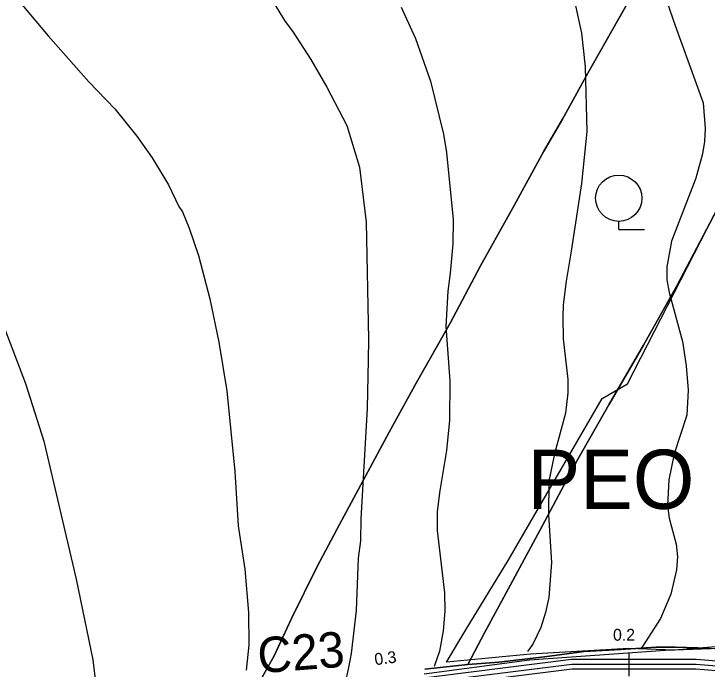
# Model space of a CAD drawing. Extents: x -662620 to -656370, y -1067090 to -1062990.
# Drawn here: x -658981.3 to -658688.1, y -1066386.4 to -1066109.2 of the extents above; entities that cross this region are included whole.
import ezdxf

# ---------------------------------------------------------------- set-up
doc = ezdxf.new("R2010")
doc.units = 0
for name, color, linetype in [('Default', 7, 'Continuous'), ('HRANICE_KATASTRÁLNÍHO_ÚZEMÍ', 7, 'Continuous'), ('Organizacni_opatreni_ochranne_zatravnení__protierozni_rozmistovani_plodin__osevni_postup__stridani_plodin', 7, 'Continuous'), ('ORNÁ_PŮDA_-_STÁVAJÍCÍ', 7, 'Continuous'), ('OSTATNÍ_PLOCHA_-_STÁVAJÍCÍ', 7, 'Continuous'), ('OVOCNÝ_SAD_-_STÁVAJÍCÍ', 7, 'Continuous'), ('OVOCNÝ_SAD_-_ZNAČKA', 7, 'Continuous'), ('POLNÍ_CESTA_STÁVAJÍCÍ_-_KRAJ', 7, 'Continuous'), ('POLNÍ_CESTA_STÁVAJÍCÍ_-_OSA', 7, 'Continuous'), ('Popis_objektú_polních_cest_stávajících', 7, 'Continuous'), ('VRSTEVNICE_ZDŮRAZNĚNÁ', 7, 'Continuous'), ('VRSTEVNICE_ZÁKLADNÍ', 7, 'Continuous')]:
    doc.layers.add(name, color=color, linetype=linetype)

msp = doc.modelspace()

# ---------------------------------------------------------------- linework, layer by layer
at = {"layer": 'HRANICE_KATASTRÁLNÍHO_ÚZEMÍ'}
msp.add_lwpolyline([(-658807.8, -1066388.34), (-658763.27, -1066382.42), (-658705.81, -1066378.41), (-658644.15, -1066376.09), (-658640.46, -1066376.58), (-658612.67, -1066385.38), (-658599.32, -1066389.61)], dxfattribs=at)
at = {"layer": 'Organizacni_opatreni_ochranne_zatravnení__protierozni_rozmistovani_plodin__osevni_postup__stridani_plodin'}
msp.add_lwpolyline([(-658515.32, -1066087.97), (-658611.96, -1066385.11), (-658646.2, -1066373.85), (-658701.92, -1066378.35), (-658721.2, -1066377.7), (-658762.8, -1066380.1), (-658798.28, -1066383.49), (-658790.2, -1066369.8), (-658772.2, -1066340.5), (-658732.5, -1066271.9), (-658721.7, -1066265.7), (-658679.4, -1066183.2), (-658621.96, -1066065.74), (-658571.37, -1066075.89), (-658543.99, -1066081.97)], close=True, dxfattribs=at)
at = {"layer": 'ORNÁ_PŮDA_-_STÁVAJÍCÍ'}
for p, q in [((-658713.12, -1066089.31), (-658725.43, -1066111.17)), ((-658725.43, -1066111.17), (-658738.48, -1066134.29)), ((-658738.48, -1066134.29), (-658749.28, -1066153.83)), ((-658749.28, -1066153.83), (-658757.17, -1066167.26)), ((-658757.17, -1066167.26), (-658769.64, -1066190.35)), ((-658769.64, -1066190.35), (-658783.88, -1066215.86)), ((-658700.9, -1066224.3), (-658683.93, -1066192.16)), ((-658783.88, -1066215.86), (-658796.78, -1066240.04)), ((-658714.94, -1066249.3), (-658700.9, -1066224.3)), ((-658796.78, -1066240.04), (-658810.97, -1066265.15)), ((-658729.63, -1066274.64), (-658714.94, -1066249.3)), ((-658810.97, -1066265.15), (-658822.53, -1066286.09)), ((-658742.91, -1066297.84), (-658729.63, -1066274.64)), ((-658822.53, -1066286.09), (-658832.6, -1066304.76)), ((-658758.91, -1066327.69), (-658742.91, -1066297.84)), ((-658832.6, -1066304.76), (-658843.53, -1066325.14)), ((-658843.53, -1066325.14), (-658853.1, -1066342.96)), ((-658773.05, -1066354.13), (-658758.91, -1066327.69)), ((-658853.1, -1066342.96), (-658863.83, -1066364.98)), ((-658782.28, -1066371.01), (-658773.05, -1066354.13)), ((-658863.83, -1066364.98), (-658871.22, -1066380.79)), ((-658789.25, -1066384.41), (-658782.28, -1066371.01)), ((-658709.66, -1066377.1), (-658724.68, -1066378.11)), ((-658701.54, -1066377.15), (-658709.66, -1066377.1)), ((-658740.07, -1066378.97), (-658756.9, -1066381.11)), ((-658724.68, -1066378.11), (-658740.07, -1066378.97)), ((-658687.26, -1066377.58), (-658701.54, -1066377.15)), ((-658871.22, -1066380.79), (-658877.55, -1066391.99)), ((-658756.9, -1066381.11), (-658776.23, -1066383.42)), ((-658776.23, -1066383.42), (-658789.25, -1066384.41))]:
    msp.add_line(p, q, dxfattribs=at)
for points in [[(-658713.12, -1066089.31), (-658725.43, -1066111.17), (-658738.48, -1066134.29), (-658749.28, -1066153.83), (-658757.17, -1066167.26), (-658769.64, -1066190.35), (-658783.88, -1066215.86), (-658796.78, -1066240.04), (-658810.97, -1066265.15), (-658822.53, -1066286.09), (-658832.6, -1066304.76), (-658843.53, -1066325.14), (-658853.1, -1066342.96), (-658863.83, -1066364.98), (-658871.22, -1066380.79), (-658877.55, -1066391.99)], [(-658687.26, -1066377.58), (-658701.54, -1066377.15), (-658709.66, -1066377.1), (-658724.68, -1066378.11), (-658740.07, -1066378.97), (-658756.9, -1066381.11), (-658776.23, -1066383.42), (-658789.25, -1066384.41), (-658782.28, -1066371.01), (-658773.05, -1066354.13), (-658758.91, -1066327.69), (-658742.91, -1066297.84), (-658729.63, -1066274.64), (-658714.94, -1066249.3), (-658700.9, -1066224.3), (-658683.93, -1066192.16)]]:
    msp.add_lwpolyline(points, dxfattribs=at)
at = {"layer": 'OSTATNÍ_PLOCHA_-_STÁVAJÍCÍ'}
for p, q in [((-658724.68, -1066378.11), (-658709.66, -1066377.1)), ((-658724.68, -1066378.11), (-658709.66, -1066377.1)), ((-658709.66, -1066377.1), (-658701.54, -1066377.15)), ((-658709.66, -1066377.1), (-658701.54, -1066377.15)), ((-658756.9, -1066381.11), (-658740.07, -1066378.97)), ((-658756.9, -1066381.11), (-658740.07, -1066378.97)), ((-658740.07, -1066378.97), (-658724.68, -1066378.11)), ((-658740.07, -1066378.97), (-658724.68, -1066378.11)), ((-658701.54, -1066377.15), (-658687.26, -1066377.58)), ((-658701.54, -1066377.15), (-658687.26, -1066377.58)), ((-658776.23, -1066383.42), (-658756.9, -1066381.11)), ((-658776.23, -1066383.42), (-658756.9, -1066381.11)), ((-658807.43, -1066386.38), (-658789.25, -1066384.41)), ((-658807.43, -1066386.38), (-658789.25, -1066384.41)), ((-658789.25, -1066384.41), (-658776.23, -1066383.42)), ((-658789.25, -1066384.41), (-658776.23, -1066383.42))]:
    msp.add_line(p, q, dxfattribs=at)
msp.add_lwpolyline([(-658807.43, -1066386.38), (-658789.25, -1066384.41), (-658776.23, -1066383.42), (-658756.9, -1066381.11), (-658740.07, -1066378.97), (-658724.68, -1066378.11), (-658709.66, -1066377.1), (-658701.54, -1066377.15), (-658687.26, -1066377.58), (-658672.12, -1066378.24), (-658659, -1066379.52), (-658644.1, -1066381.07), (-658627.93, -1066382.83), (-658615.46, -1066385), (-658583.4, -1066395.38)], dxfattribs=at)
msp.add_lwpolyline([(-658807.43, -1066386.38), (-658789.25, -1066384.41), (-658776.23, -1066383.42), (-658756.9, -1066381.11), (-658740.07, -1066378.97), (-658724.68, -1066378.11), (-658709.66, -1066377.1), (-658701.54, -1066377.15), (-658687.26, -1066377.58), (-658672.12, -1066378.24), (-658659, -1066379.52), (-658644.1, -1066381.07), (-658627.93, -1066382.83), (-658615.46, -1066385), (-658583.4, -1066395.38)], dxfattribs=at)
at = {"layer": 'OVOCNÝ_SAD_-_STÁVAJÍCÍ'}
for p, q in [((-658725.43, -1066111.17), (-658713.12, -1066089.31)), ((-658738.48, -1066134.29), (-658725.43, -1066111.17)), ((-658749.28, -1066153.83), (-658738.48, -1066134.29)), ((-658757.17, -1066167.26), (-658749.28, -1066153.83)), ((-658769.64, -1066190.35), (-658757.17, -1066167.26)), ((-658783.88, -1066215.86), (-658769.64, -1066190.35)), ((-658683.93, -1066192.16), (-658700.9, -1066224.3)), ((-658796.78, -1066240.04), (-658783.88, -1066215.86)), ((-658700.9, -1066224.3), (-658714.94, -1066249.3)), ((-658810.97, -1066265.15), (-658796.78, -1066240.04)), ((-658714.94, -1066249.3), (-658729.63, -1066274.64)), ((-658822.53, -1066286.09), (-658810.97, -1066265.15)), ((-658729.63, -1066274.64), (-658742.91, -1066297.84)), ((-658832.6, -1066304.76), (-658822.53, -1066286.09)), ((-658742.91, -1066297.84), (-658758.91, -1066327.69)), ((-658843.53, -1066325.14), (-658832.6, -1066304.76)), ((-658853.1, -1066342.96), (-658843.53, -1066325.14)), ((-658758.91, -1066327.69), (-658773.05, -1066354.13)), ((-658863.83, -1066364.98), (-658853.1, -1066342.96)), ((-658773.05, -1066354.13), (-658782.28, -1066371.01)), ((-658871.22, -1066380.79), (-658863.83, -1066364.98)), ((-658782.28, -1066371.01), (-658789.25, -1066384.41)), ((-658877.55, -1066391.99), (-658871.22, -1066380.79)), ((-658789.25, -1066384.41), (-658807.43, -1066386.38))]:
    msp.add_line(p, q, dxfattribs=at)
for points in [[(-658877.55, -1066391.99), (-658871.22, -1066380.79), (-658863.83, -1066364.98), (-658853.1, -1066342.96), (-658843.53, -1066325.14), (-658832.6, -1066304.76), (-658822.53, -1066286.09), (-658810.97, -1066265.15), (-658796.78, -1066240.04), (-658783.88, -1066215.86), (-658769.64, -1066190.35), (-658757.17, -1066167.26), (-658749.28, -1066153.83), (-658738.48, -1066134.29), (-658725.43, -1066111.17), (-658713.12, -1066089.31)], [(-658633.64, -1066100.29), (-658649.35, -1066128.19), (-658665.84, -1066158.69), (-658683.93, -1066192.16), (-658700.9, -1066224.3), (-658714.94, -1066249.3), (-658729.63, -1066274.64), (-658742.91, -1066297.84), (-658758.91, -1066327.69), (-658773.05, -1066354.13), (-658782.28, -1066371.01), (-658789.25, -1066384.41), (-658807.43, -1066386.38)]]:
    msp.add_lwpolyline(points, dxfattribs=at)
at = {"layer": 'OVOCNÝ_SAD_-_ZNAČKA'}
for points in [[(-658725.47, -1066200.47), (-658725.47, -1066197)], [(-658725.47, -1066200.47), (-658714.63, -1066200.47)]]:
    msp.add_lwpolyline(points, dxfattribs=at)
msp.add_circle((-658725.47, -1066187.21), 9.79, dxfattribs=at)
at = {"layer": 'POLNÍ_CESTA_STÁVAJÍCÍ_-_KRAJ'}
for points in [[(-658524.77, -1066416.91), (-658585.14, -1066399.5), (-658627.95, -1066387.63), (-658692.63, -1066382.35), (-658745.41, -1066382.35), (-658844.82, -1066394.86), (-658910.58, -1066405.85), (-659008.67, -1066433.22), (-659055.89, -1066439.26), (-659092.46, -1066437.38), (-659149.26, -1066425.87), (-659161.27, -1066431.66), (-659178.7, -1066451.74), (-659206.01, -1066461.71), (-659282.28, -1066460.95), (-659319.31, -1066453.29)], [(-658525.87, -1066420.75), (-658586.23, -1066403.35), (-658628.66, -1066391.58), (-658692.79, -1066386.35), (-658745.16, -1066386.35), (-658844.24, -1066398.82), (-658909.71, -1066409.76), (-659007.88, -1066437.15), (-659055.74, -1066443.28), (-659092.96, -1066441.36), (-659148.74, -1066430.05), (-659158.79, -1066434.91), (-659176.35, -1066455.14), (-659205.33, -1066465.71), (-659282.71, -1066464.95), (-659320.12, -1066457.21)]]:
    msp.add_lwpolyline(points, dxfattribs=at)
at = {"layer": 'POLNÍ_CESTA_STÁVAJÍCÍ_-_OSA'}
for points in [[(-658721.04, -1066389.35), (-658721.04, -1066379.35)], [(-658525.32, -1066418.83), (-658585.69, -1066401.42), (-658628.3, -1066389.61), (-658692.71, -1066384.35), (-658745.29, -1066384.35), (-658844.53, -1066396.84), (-658910.15, -1066407.8), (-659008.28, -1066435.19), (-659055.82, -1066441.27), (-659092.71, -1066439.37), (-659149, -1066427.96), (-659160.03, -1066433.28), (-659177.52, -1066453.44), (-659205.67, -1066463.71), (-659282.5, -1066462.95), (-659319.71, -1066455.25)]]:
    msp.add_lwpolyline(points, dxfattribs=at)
at = {"layer": 'VRSTEVNICE_ZDŮRAZNĚNÁ'}
for points in [[(-658707.22, -1066097.88), (-658701.63, -1066114.21), (-658689.74, -1066146.89), (-658688.88, -1066157.78), (-658689.16, -1066163.23), (-658690.02, -1066168.39), (-658692.89, -1066178.71), (-658703.21, -1066205.36), (-658705.07, -1066216.26), (-658705.07, -1066221.7), (-658704.07, -1066227.15), (-658698.48, -1066247.78), (-658696.9, -1066258.1), (-658696.04, -1066268.42), (-658696.61, -1066279.03), (-658702.06, -1066295.37), (-658704.21, -1066306.26), (-658704.78, -1066317.15), (-658704.07, -1066322.6), (-658701.2, -1066333.49), (-658700.63, -1066338.93), (-658701.06, -1066344.38), (-658703.49, -1066354.7), (-658707.79, -1066365.02), (-658715.68, -1066377.2)], [(-658989.55, -1066231.45), (-658976.37, -1066265.56)], [(-658976.37, -1066265.56), (-658968.63, -1066289.92), (-658955.01, -1066348.39), (-658947.99, -1066382.5), (-658946.27, -1066396.55), (-658946.42, -1066416.47)]]:
    msp.add_lwpolyline(points, dxfattribs=at)
at = {"layer": 'VRSTEVNICE_ZÁKLADNÍ'}
for points in [[(-658984.68, -1066097.16), (-658966.77, -1066118.51), (-658949.57, -1066138), (-658938.68, -1066149.47), (-658929.36, -1066160.93), (-658922.91, -1066170.11), (-658915.89, -1066181.57), (-658911.59, -1066190.74), (-658910.01, -1066193.04), (-658907.15, -1066199.92), (-658903.28, -1066211.38), (-658898.4, -1066229.73), (-658894.68, -1066248.07), (-658891.24, -1066268.71), (-658887.8, -1066302.82), (-658886.51, -1066325.75), (-658883.64, -1066344.09), (-658882.07, -1066362.44), (-658881.92, -1066376.2), (-658883.02, -1066386.8)], [(-658984.68, -1066097.16), (-658966.77, -1066118.51), (-658949.57, -1066138), (-658938.68, -1066149.47), (-658929.36, -1066160.93), (-658922.91, -1066170.11), (-658915.89, -1066181.57), (-658911.59, -1066190.74), (-658910.01, -1066193.04), (-658907.15, -1066199.92), (-658903.28, -1066211.38), (-658898.4, -1066229.73), (-658894.68, -1066248.07), (-658891.24, -1066268.71), (-658887.8, -1066302.82), (-658886.51, -1066325.75), (-658883.64, -1066344.09), (-658882.07, -1066362.44), (-658881.92, -1066376.2), (-658883.02, -1066386.8)], [(-658745.63, -1066097.3), (-658741.18, -1066117.37), (-658739.61, -1066131.7), (-658738.89, -1066158.93), (-658741.18, -1066181), (-658745.62, -1066209.56), (-658747.68, -1066222.36), (-658748.92, -1066232.31), (-658749.14, -1066237.47), (-658748.92, -1066246.64), (-658747.06, -1066263.84), (-658747.06, -1066269.57), (-658747.92, -1066278.17), (-658752.65, -1066295.37), (-658755.09, -1066306.83), (-658755.23, -1066321.16), (-658753.94, -1066341.23), (-658755.09, -1066356.13), (-658756.38, -1066362.44), (-658758.38, -1066368.74), (-658761.82, -1066375.77), (-658764.06, -1066378.87)], [(-658745.63, -1066097.3), (-658741.18, -1066117.37), (-658739.61, -1066131.7), (-658738.89, -1066158.93), (-658741.18, -1066181), (-658745.62, -1066209.56), (-658747.68, -1066222.36), (-658748.92, -1066232.31), (-658749.14, -1066237.47), (-658748.92, -1066246.64), (-658747.06, -1066263.84), (-658747.06, -1066269.57), (-658747.92, -1066278.17), (-658752.65, -1066295.37), (-658755.09, -1066306.83), (-658755.23, -1066321.16), (-658753.94, -1066341.23), (-658755.09, -1066356.13), (-658756.38, -1066362.44), (-658758.38, -1066368.74), (-658761.82, -1066375.77), (-658764.06, -1066378.87)], [(-658871.46, -1066104.47), (-658866.59, -1066112.49), (-658863.44, -1066116.51), (-658855.7, -1066128.55), (-658848.96, -1066140.3), (-658840.5, -1066156.49), (-658835.2, -1066174.12), (-658832.34, -1066197.34), (-658831.29, -1066246.94), (-658831.45, -1066255.52), (-658831.91, -1066276.16), (-658834.63, -1066322.88), (-658834.77, -1066332.06), (-658835.63, -1066339.51), (-658836.49, -1066361.58), (-658838.66, -1066379.71), (-658839.07, -1066382.03), (-658839.94, -1066386.35), (-658841.22, -1066392.1)], [(-658871.46, -1066104.47), (-658866.59, -1066112.49), (-658863.44, -1066116.51), (-658855.7, -1066128.55), (-658848.96, -1066140.3), (-658840.5, -1066156.49), (-658835.2, -1066174.12), (-658832.34, -1066197.34), (-658831.29, -1066246.94), (-658831.45, -1066255.52), (-658831.91, -1066276.16), (-658834.63, -1066322.88), (-658834.77, -1066332.06), (-658835.63, -1066339.51), (-658836.49, -1066361.58), (-658838.66, -1066379.71), (-658839.07, -1066382.03), (-658839.94, -1066386.35), (-658841.22, -1066392.1)], [(-658817.57, -1066106.47), (-658811.41, -1066119.66), (-658805.11, -1066137.72), (-658799.66, -1066160.08), (-658798.37, -1066167.81), (-658795.5, -1066196.19), (-658795.65, -1066206.51), (-658796.8, -1066218.88), (-658797.8, -1066226.57), (-658798.66, -1066241.48), (-658796.94, -1066264.41), (-658797.08, -1066281.03), (-658798.37, -1066293.93), (-658801.12, -1066310.77), (-658802.24, -1066319.73), (-658802.24, -1066327.76), (-658799.23, -1066354.13), (-658799.09, -1066361.86), (-658799.8, -1066370.18), (-658801.23, -1066378.78), (-658803.53, -1066385.23)], [(-658817.57, -1066106.47), (-658811.41, -1066119.66), (-658805.11, -1066137.72), (-658799.66, -1066160.08), (-658798.37, -1066167.81), (-658795.5, -1066196.19), (-658795.65, -1066206.51), (-658796.8, -1066218.88), (-658797.8, -1066226.57), (-658798.66, -1066241.48), (-658796.94, -1066264.41), (-658797.08, -1066281.03), (-658798.37, -1066293.93), (-658801.12, -1066310.77), (-658802.24, -1066319.73), (-658802.24, -1066327.76), (-658799.23, -1066354.13), (-658799.09, -1066361.86), (-658799.8, -1066370.18), (-658801.23, -1066378.78), (-658803.53, -1066385.23)]]:
    msp.add_lwpolyline(points, dxfattribs=at)

# ---------------------------------------------------------------- texts
at = {"layer": 'Default'}
msp.add_text('0.2', height=5, dxfattribs=at).set_placement((-658727.87, -1066374.35))
msp.add_text('0.3', height=5, rotation=7.1717, dxfattribs=at).set_placement((-658828.49, -1066384.74))
at = {"layer": 'Organizacni_opatreni_ochranne_zatravnení__protierozni_rozmistovani_plodin__osevni_postup__stridani_plodin'}
msp.add_text('PEO 1, os. postup 1', height=25, dxfattribs=at).set_placement((-658764.08, -1066318.59))
at = {"layer": 'Popis_objektú_polních_cest_stávajících'}
msp.add_text('C23', height=15, rotation=4.5, dxfattribs=at).set_placement((-658877.68, -1066388.18))

doc.saveas('drawing.dxf')
